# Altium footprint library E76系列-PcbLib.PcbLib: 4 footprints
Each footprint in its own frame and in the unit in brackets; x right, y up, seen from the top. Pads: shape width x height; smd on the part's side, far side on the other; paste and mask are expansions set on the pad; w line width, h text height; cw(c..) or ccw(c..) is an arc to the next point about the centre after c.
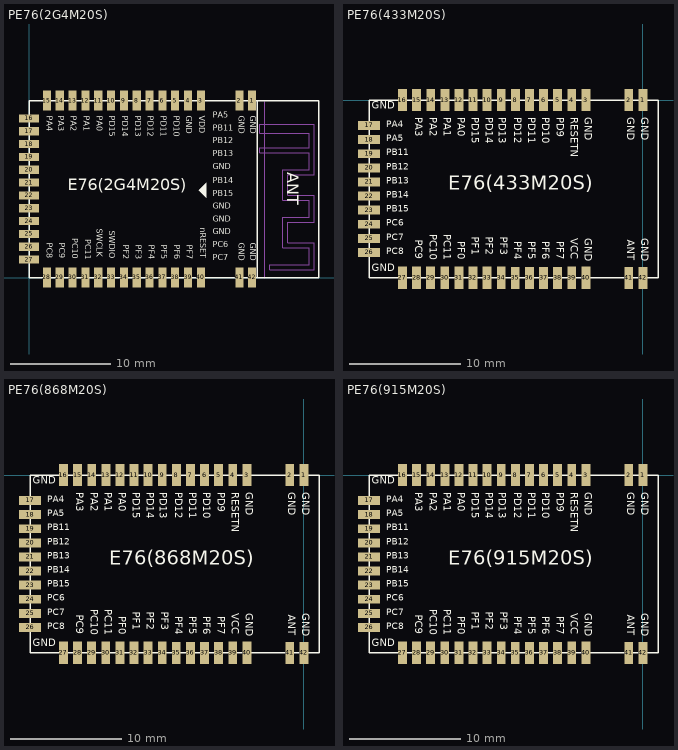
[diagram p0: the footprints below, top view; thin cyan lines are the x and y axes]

## PE76(2G4M20S) [mm] "28.7mm*17.5mm*2.60mm-S"
pads (42):
  rect 0.8x2 smd: 1(22.081,17.517) 2(20.811,17.517) 3(17.001,17.517) 4(15.731,17.517) 5(14.461,17.517) 6(13.191,17.517) 7(11.921,17.517) 8(10.651,17.517) 9(9.381,17.517) 10(8.111,17.517) 11(6.841,17.517) 12(5.571,17.517) 13(4.301,17.517) 14(3.031,17.517) 15(1.761,17.517) 28(1.761,0.017) 29(3.031,0.017) 30(4.301,0.017) 31(5.571,0.017) 32(6.841,0.017) 33(8.111,0.017) 34(9.381,0.017) 35(10.651,0.017) 36(11.921,0.017) 37(13.191,0.017) 38(14.461,0.017) 39(15.731,0.017) 40(17.001,0.017) 41(20.811,0.017) 42(22.081,0.017)
  rect 2x0.8 smd: 16(-0.004,15.752) 17(-0.004,14.482) 18(-0.004,13.212) 19(-0.004,11.942) 20(-0.004,10.672) 21(-0.004,9.402) 22(-0.004,8.132) 23(-0.004,6.862) 24(-0.004,5.592) 25(-0.004,4.322) 26(-0.004,3.052) 27(-0.004,1.782)
Top Overlay:
  region: 17.526,7.907 16.797,8.636 17.526,9.365
  lines w0.127: 22.604,0 22.604,17.52 ; 0,0 28.7,0 28.7,17.52 0,17.52 0,0
  text "GND" at 21.717,3.429 h1
  text "GND" at 20.574,3.429 h1
  text "PC7" at 18.161,1.524 h1
  text "PC6" at 18.161,2.794 h1
  text "GND" at 18.161,4.064 h1
  text "GND" at 18.161,5.334 h1
  text "GND" at 18.161,6.604 h1
  text "PB15" at 18.161,7.874 h1
  text "PB14" at 18.161,9.144 h1
  text "GND" at 18.161,10.541 h1
  text "PB13" at 18.161,11.811 h1
  text "PB12" at 18.161,13.081 h1
  text "PB11" at 18.161,14.351 h1
  text "PA5" at 18.161,15.621 h1
  text "ANT" at 25.146,10.414 h2
  text "PC8" at 1.524,3.429 h1
  text "PC9" at 2.794,3.429 h1
  text "PC10" at 4.069,3.884 h1
  text "PC11" at 5.334,3.81 h1
  text "SWCLK" at 6.477,4.826 h1
  text "SWDIO" at 7.725,4.646 h1
  text "PF2" at 9.101,3.249 h1
  text "PF3" at 10.374,3.249 h1
  text "PF4" at 11.623,3.249 h1
  text "PF5" at 12.896,3.249 h1
  text "PF6" at 14.157,3.249 h1
  text "PF7" at 15.418,3.249 h1
  text "nRESET" at 16.764,4.953 h1
  text "VDD" at 16.637,16.002 h1
  text "GND" at 15.367,16.002 h1
  text "PD10" at 14.097,16.002 h1
  text "PD11" at 12.827,16.002 h1
  text "PD12" at 11.557,16.002 h1
  text "PD13" at 10.287,16.002 h1
  text "PD14" at 9.017,16.002 h1
  text "PD15" at 7.747,16.002 h1
  text "PA0" at 6.477,16.002 h1
  text "PA1" at 5.207,16.002 h1
  text "PA2" at 3.937,16.002 h1
  text "PA3" at 2.667,16.002 h1
  text "PA4" at 1.524,16.002 h1
  text "E76(2G4M20S)" at 3.81,8.255 h2
  text "GND" at 20.574,16.002 h1
  text "GND" at 21.717,16.002 h1
Mechanical 3:
  lines w0.005: 23.348,11.764 23.348,12.264 ; 24.744,0.764 28.248,0.764 ; 25.108,5.464 25.108,5.964 ; 27.748,0.764 23.808,0.764 23.808,1.264 27.748,1.264 27.748,2.964 25.108,2.964 25.108,5.964 ; 23.348,14.264 22.848,14.264 22.848,15.164 23.348,15.164 ; 23.348,14.264 23.348,15.164 ; 23.348,14.264 27.748,14.264 ; 23.348,15.164 27.748,15.164 28.248,15.164 28.248,10.164 27.748,10.164 25.608,10.164 25.608,8.164 28.248,8.164 ; 25.108,5.964 27.748,5.964 27.748,7.664 25.108,7.664 25.108,8.164 25.108,10.164 25.108,10.664 27.748,10.664 27.748,12.364 22.848,12.364 22.848,12.864 27.748,12.864 ; 25.608,3.464 25.608,5.464 ; 25.608,3.464 28.248,3.464 ; 25.608,3.464 25.608,5.464 ; 25.608,5.464 28.248,5.464 ; 27.748,12.864 27.748,14.264 ; 27.748,12.864 27.748,14.264 ; 28.248,0.764 28.248,3.464 ; 28.248,0.764 28.248,3.464 ; 28.248,5.464 28.248,8.164 ; 28.248,5.464 28.248,8.164
Mechanical 4:
  lines w0.005: 23.348,-0.047 23.348,17.4

## PE76(433M20S) [mm] "26.1mm*16.1mm*2.60mm-S"
pads (42):
  rect 0.8x2 smd: 1(0,0) 2(-1.27,0) 3(-5.132,0) 4(-6.402,0) 5(-7.672,0) 6(-8.942,0) 7(-10.212,0) 8(-11.482,0) 9(-12.752,0) 10(-14.022,0) 11(-15.289,0.001) 12(-16.559,0.001) 13(-17.829,0.001) 14(-19.099,0.001) 15(-20.372,0) 16(-21.642,0) 27(-21.642,-16) 28(-20.372,-16) 29(-19.102,-16) 30(-17.832,-16) 31(-16.562,-16) 32(-15.292,-16) 33(-14.022,-16) 34(-12.752,-16) 35(-11.485,-16) 36(-10.215,-16) 37(-8.945,-16) 38(-7.675,-16) 39(-6.402,-16) 40(-5.132,-16) 41(-1.27,-16.006) 42(0,-16.006)
  rect 2x0.8 smd: 17(-24.642,-2.287) 18(-24.642,-3.557) 19(-24.642,-4.827) 20(-24.642,-6.097) 21(-24.642,-7.367) 22(-24.642,-8.637) 23(-24.642,-9.907) 24(-24.642,-11.177) 25(-24.642,-12.444) 26(-24.642,-13.714)
Top Overlay:
  lines w0.127: -24.642,-16 -24.642,-7.72 -24.642,0 1.358,0 1.358,-15.999 -0.263,-15.999 -2.654,-15.999 -24.642,-16
  text "E76(433M20S)" at -17.526,-8.509 h2.2
  text "GND" at -24.384,-15.621 h1.1
  text "GND" at -1.651,-1.524 h1.1
  text "ANT" at -1.651,-12.573 h1.1
  text "PC8" at -23.114,-14.097 h1
  text "PC7" at -23.114,-12.827 h1
  text "PC6" at -23.114,-11.557 h1
  text "PB15" at -23.114,-10.287 h1
  text "PB14" at -23.114,-9.017 h1
  text "PB13" at -23.114,-7.747 h1
  text "PB12" at -23.114,-6.477 h1
  text "PB11" at -23.114,-5.207 h1
  text "PA5" at -23.114,-3.937 h1
  text "PA4" at -23.114,-2.667 h1
  text "PA3" at -20.701,-1.524 h1.1
  text "PA2" at -19.431,-1.524 h1.1
  text "PA1" at -18.161,-1.524 h1.1
  text "PA0" at -16.891,-1.524 h1.1
  text "PD15" at -15.621,-1.524 h1.1
  text "PD14" at -14.351,-1.524 h1.1
  text "PD13" at -13.208,-1.524 h1.1
  text "PD12" at -11.811,-1.524 h1.1
  text "PD11" at -10.541,-1.524 h1.1
  text "PD10" at -9.271,-1.524 h1.1
  text "PD9" at -8.001,-1.524 h1.1
  text "PC11" at -18.161,-12.065 h1.1
  text "PC10" at -19.431,-12.065 h1.1
  text "PC9" at -20.701,-12.573 h1.1
  text "GND" at -0.381,-1.524 h1.1
  text "GND" at -0.381,-12.446 h1.1
  text "GND" at -5.461,-12.446 h1.1
  text "VCC" at -6.731,-12.446 h1.1
  text "PF7" at -8.001,-12.7 h1.1
  text "PF6" at -9.271,-12.7 h1.1
  text "PF5" at -10.541,-12.7 h1.1
  text "PF4" at -11.811,-12.7 h1.1
  text "PF3" at -13.081,-12.319 h1.1
  text "PF2" at -14.351,-12.319 h1.1
  text "PF1" at -15.621,-12.319 h1.1
  text "PF0" at -16.891,-12.7 h1.1
  text "GND" at -5.461,-1.524 h1.1
  text "RESETN" at -6.731,-1.524 h1.1
  text "GND" at -24.384,-1.016 h1.1
Keep-Out Layer:
  lines w0.1: -24.642,-7.72 -24.642,-7.72 ; -2.654,-16 -2.654,-15.999

## PE76(868M20S) [mm] "26.1mm*16.1mm*2.60mm-S"
pads (42):
  rect 0.8x2 smd: 1(0,0) 2(-1.27,0) 3(-5.132,0) 4(-6.402,0) 5(-7.672,0) 6(-8.942,0) 7(-10.212,0) 8(-11.482,0) 9(-12.752,0) 10(-14.022,0) 11(-15.289,0.001) 12(-16.559,0.001) 13(-17.829,0.001) 14(-19.099,0.001) 15(-20.372,0) 16(-21.642,0) 27(-21.642,-16) 28(-20.372,-16) 29(-19.102,-16) 30(-17.832,-16) 31(-16.562,-16) 32(-15.292,-16) 33(-14.022,-16) 34(-12.752,-16) 35(-11.485,-16) 36(-10.215,-16) 37(-8.945,-16) 38(-7.675,-16) 39(-6.402,-16) 40(-5.132,-16) 41(-1.27,-16.006) 42(0,-16.006)
  rect 2x0.8 smd: 17(-24.642,-2.287) 18(-24.642,-3.557) 19(-24.642,-4.827) 20(-24.642,-6.097) 21(-24.642,-7.367) 22(-24.642,-8.637) 23(-24.642,-9.907) 24(-24.642,-11.177) 25(-24.642,-12.444) 26(-24.642,-13.714)
Top Overlay:
  lines w0.127: -24.642,-16 -2.654,-16 -0.263,-15.999 1.358,-15.999 1.358,0 -24.642,0 -24.642,-7.72 -24.642,-16
  text "GND" at -24.384,-1.016 h1.1
  text "RESETN" at -6.731,-1.524 h1.1
  text "GND" at -5.461,-1.524 h1.1
  text "PF0" at -16.891,-12.7 h1.1
  text "PF1" at -15.621,-12.319 h1.1
  text "PF2" at -14.351,-12.319 h1.1
  text "PF3" at -13.081,-12.319 h1.1
  text "PF4" at -11.811,-12.7 h1.1
  text "PF5" at -10.541,-12.7 h1.1
  text "PF6" at -9.271,-12.7 h1.1
  text "PF7" at -8.001,-12.7 h1.1
  text "VCC" at -6.731,-12.446 h1.1
  text "GND" at -5.461,-12.446 h1.1
  text "GND" at -0.381,-12.446 h1.1
  text "GND" at -0.381,-1.524 h1.1
  text "PC9" at -20.701,-12.573 h1.1
  text "PC10" at -19.431,-12.065 h1.1
  text "PC11" at -18.161,-12.065 h1.1
  text "PD9" at -8.001,-1.524 h1.1
  text "PD10" at -9.271,-1.524 h1.1
  text "PD11" at -10.541,-1.524 h1.1
  text "PD12" at -11.811,-1.524 h1.1
  text "PD13" at -13.208,-1.524 h1.1
  text "PD14" at -14.351,-1.524 h1.1
  text "PD15" at -15.621,-1.524 h1.1
  text "PA0" at -16.891,-1.524 h1.1
  text "PA1" at -18.161,-1.524 h1.1
  text "PA2" at -19.431,-1.524 h1.1
  text "PA3" at -20.701,-1.524 h1.1
  text "PA4" at -23.114,-2.667 h1
  text "PA5" at -23.114,-3.937 h1
  text "PB11" at -23.114,-5.207 h1
  text "PB12" at -23.114,-6.477 h1
  text "PB13" at -23.114,-7.747 h1
  text "PB14" at -23.114,-9.017 h1
  text "PB15" at -23.114,-10.287 h1
  text "PC6" at -23.114,-11.557 h1
  text "PC7" at -23.114,-12.827 h1
  text "PC8" at -23.114,-14.097 h1
  text "ANT" at -1.651,-12.573 h1.1
  text "GND" at -1.651,-1.524 h1.1
  text "GND" at -24.384,-15.621 h1.1
  text "E76(868M20S)" at -17.526,-8.509 h2.2
Keep-Out Layer:
  lines w0.1: -24.642,-7.72 -24.642,-7.72 ; -2.654,-16 -2.654,-15.999

## PE76(915M20S) [mm] "26.1mm*16.1mm*2.60mm-S"
pads (42):
  rect 0.8x2 smd: 1(0,0) 2(-1.27,0) 3(-5.132,0) 4(-6.402,0) 5(-7.672,0) 6(-8.942,0) 7(-10.212,0) 8(-11.482,0) 9(-12.752,0) 10(-14.022,0) 11(-15.289,0.001) 12(-16.559,0.001) 13(-17.829,0.001) 14(-19.099,0.001) 15(-20.372,0) 16(-21.642,0) 27(-21.642,-16) 28(-20.372,-16) 29(-19.102,-16) 30(-17.832,-16) 31(-16.562,-16) 32(-15.292,-16) 33(-14.022,-16) 34(-12.752,-16) 35(-11.485,-16) 36(-10.215,-16) 37(-8.945,-16) 38(-7.675,-16) 39(-6.402,-16) 40(-5.132,-16) 41(-1.27,-16.006) 42(0,-16.006)
  rect 2x0.8 smd: 17(-24.642,-2.287) 18(-24.642,-3.557) 19(-24.642,-4.827) 20(-24.642,-6.097) 21(-24.642,-7.367) 22(-24.642,-8.637) 23(-24.642,-9.907) 24(-24.642,-11.177) 25(-24.642,-12.444) 26(-24.642,-13.714)
Top Overlay:
  lines w0.127: -24.642,-16 -24.642,-7.72 -24.642,0 1.358,0 1.358,-15.999 -0.263,-15.999 -2.654,-15.999 -24.642,-16
  text "E76(915M20S)" at -17.526,-8.509 h2.2
  text "GND" at -24.384,-15.621 h1.1
  text "GND" at -1.651,-1.524 h1.1
  text "ANT" at -1.651,-12.573 h1.1
  text "PC8" at -23.114,-14.097 h1
  text "PC7" at -23.114,-12.827 h1
  text "PC6" at -23.114,-11.557 h1
  text "PB15" at -23.114,-10.287 h1
  text "PB14" at -23.114,-9.017 h1
  text "PB13" at -23.114,-7.747 h1
  text "PB12" at -23.114,-6.477 h1
  text "PB11" at -23.114,-5.207 h1
  text "PA5" at -23.114,-3.937 h1
  text "PA4" at -23.114,-2.667 h1
  text "PA3" at -20.701,-1.524 h1.1
  text "PA2" at -19.431,-1.524 h1.1
  text "PA1" at -18.161,-1.524 h1.1
  text "PA0" at -16.891,-1.524 h1.1
  text "PD15" at -15.621,-1.524 h1.1
  text "PD14" at -14.351,-1.524 h1.1
  text "PD13" at -13.208,-1.524 h1.1
  text "PD12" at -11.811,-1.524 h1.1
  text "PD11" at -10.541,-1.524 h1.1
  text "PD10" at -9.271,-1.524 h1.1
  text "PD9" at -8.001,-1.524 h1.1
  text "PC11" at -18.161,-12.065 h1.1
  text "PC10" at -19.431,-12.065 h1.1
  text "PC9" at -20.701,-12.573 h1.1
  text "GND" at -0.381,-1.524 h1.1
  text "GND" at -0.381,-12.446 h1.1
  text "GND" at -5.461,-12.446 h1.1
  text "VCC" at -6.731,-12.446 h1.1
  text "PF7" at -8.001,-12.7 h1.1
  text "PF6" at -9.271,-12.7 h1.1
  text "PF5" at -10.541,-12.7 h1.1
  text "PF4" at -11.811,-12.7 h1.1
  text "PF3" at -13.081,-12.319 h1.1
  text "PF2" at -14.351,-12.319 h1.1
  text "PF1" at -15.621,-12.319 h1.1
  text "PF0" at -16.891,-12.7 h1.1
  text "GND" at -5.461,-1.524 h1.1
  text "RESETN" at -6.731,-1.524 h1.1
  text "GND" at -24.384,-1.016 h1.1
Keep-Out Layer:
  lines w0.1: -24.642,-7.72 -24.642,-7.72 ; -2.654,-16 -2.654,-15.999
